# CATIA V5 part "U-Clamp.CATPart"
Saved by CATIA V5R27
Part number: U-Clamp
Bounding box of the stored display mesh (mm): x -23 to 23, y -6.5 to 6.5, z -25 to 29
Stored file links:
  E:\_Deepak\2017_Deepak\CATIA\Resources\Tutorial Files\Tutorials\c14_catia_v5_6r2016_tut\c14tut2\c14tut2.CATParts\U-Clamp_cat_v5-6r2016.CATPart
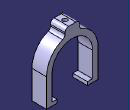
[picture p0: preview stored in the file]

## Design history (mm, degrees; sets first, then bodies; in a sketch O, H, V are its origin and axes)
Body1 (main body)
  Sketch1 on zx-plane, origin (0, 0, 0), H (-1, 0, 0), V (0, 0, 1)
    arc A1 centre (0, 0) radius 18 from (18, 0) to (-18, 0) ccw
    point P1 (-18, 0)
    point P2 (18, 0)
    line L1 (-18, 0) -> (-18, -22)
    point P3 (-18, -22)
    line L2 (-18, -22) -> (-13.5, -22)
    point P4 (-13.5, -22)
    line L3 (-13.5, -22) -> (-13.5, -25)
    point P5 (-13.5, -25)
    line L4 (-13.5, -25) -> (-23, -25)
    point P6 (-23, -25)
    line L5 (-23, -25) -> (-23, 0)
    point P7 (-23, 0)
    arc A2 centre (0, 0) radius 23 from (-23, 0) to (-6.5, 22.0624) cw
    point P9 (23, 0)
    point P10 (23, 0)
    point P11 (23, -25)
    line L6 (23, -25) -> (23, 0)
    point P12 (13.5, -25)
    line L7 (13.5, -25) -> (23, -25)
    point P13 (13.5, -22)
    line L8 (13.5, -22) -> (13.5, -25)
    point P14 (18, -22)
    line L9 (18, -22) -> (13.5, -22)
    point P15 (18, 0)
    line L10 (18, 0) -> (18, -22)
    line L11 (-6.5, 22.0624) -> (-6.5, 29)
    point P16 (-6.5, 29)
    line L12 (-6.5, 29) -> (6.5, 29)
    point P17 (6.5, 29)
    line L13 (6.5, 29) -> (6.5, 22.0624)
    point P18 (6.5, 22.0624)
    arc A3 centre (0, 0) radius 23 from (6.5, 22.0624) to (23, 0) cw
    distance L3 V = 13.5
    distance H L4 = 25
    distance V L5 = 23
    distance P16 P17 = 13
    distance L11 V = 6.5
    distance L7 L12 = 54
    distance L1 L5 = 5
    length L3 = 3
    coincidence: P1 H, P2 H, P7 H, A2 P18, A2 A3, P2 P15, P9 P10
    tangency: L1 A1, A2 L5
    horizontal: L2 H, L4 H, L12 H
    vertical: L3 V, L5 V, L11 V, L13 V
    concentricity: A2 A1
    symmetry: P7 P10 V, P6 P11 V, L5 L6 V, P5 P12 V, L4 L7 V, P4 P13 V, L3 L8 V, P3 P14 V, L2 L9 V, P1 P15 V, L1 L10 V
  Pad1: profile Sketch1, direction (0, -1, 0), length 6.5, mirrored extent
  Fillet1: radius 3.302, on 4 edges
  Sketch2 on face of Pad1, origin (-0.057, 2.6412, 29), H (1, 0, 0), V (0, 1, 0)
    point P1 (0.057, -2.6412)
    reference intersected line E1 through (0.057, 0) direction (0, 1) from yz-plane
    reference intersected line E2 through (0, -2.6412) direction (-1, 0) from zx-plane
    coincidence: E1 P1, E2 P1
  Hole1: placed by Sketch2, at (0, 0, 29) direction (0, 0, -1), diameter 4, depth 25.4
